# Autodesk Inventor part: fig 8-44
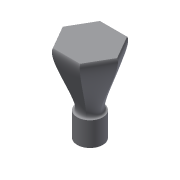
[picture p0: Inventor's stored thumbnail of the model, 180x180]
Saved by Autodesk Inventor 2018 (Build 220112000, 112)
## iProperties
Created: 2004-05
Part Number: fig 8-44
Document SubType Name: Modeling
Designer: CADCIM Technologies
Manufacturer: Standard
Standards Organization: Custom
Density: 1 g/cm^3
Material: Generic
Appearance: Default
Author: CADCIM Technologies
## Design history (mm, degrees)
sketch "Sketch1"
  geometry: C1 r 16.344 at (0, 0)
  constraints: 1 centre point
extrude "Extrusion1" new body sketch "Sketch1" distance "d0" = 30.75; taper "d1" = 0 deg
workplane "Work Plane1"
sketch "Sketch2"
  geometry: L1 (34.788, 0)-(17.394, -30.128); L2 (17.394, -30.128)-(-17.394, -30.128); L3 (-17.394, -30.128)-(-34.788, 0); L4 (-34.788, 0)-(-17.394, 30.128); L5 (-17.394, 30.128)-(17.394, 30.128); L6 (17.394, 30.128)-(34.788, 0); 2 further points
  constraints: 12 end point, 1 coincident, 12 other
loft "Loft2" sketch "Sketch2" dims "d9" = 5, "d10" = 90 deg, "d11" = 40, "d12" = 120 deg
  node "Edges2"
body "Solid1"
other parameters: "d2" = 75
